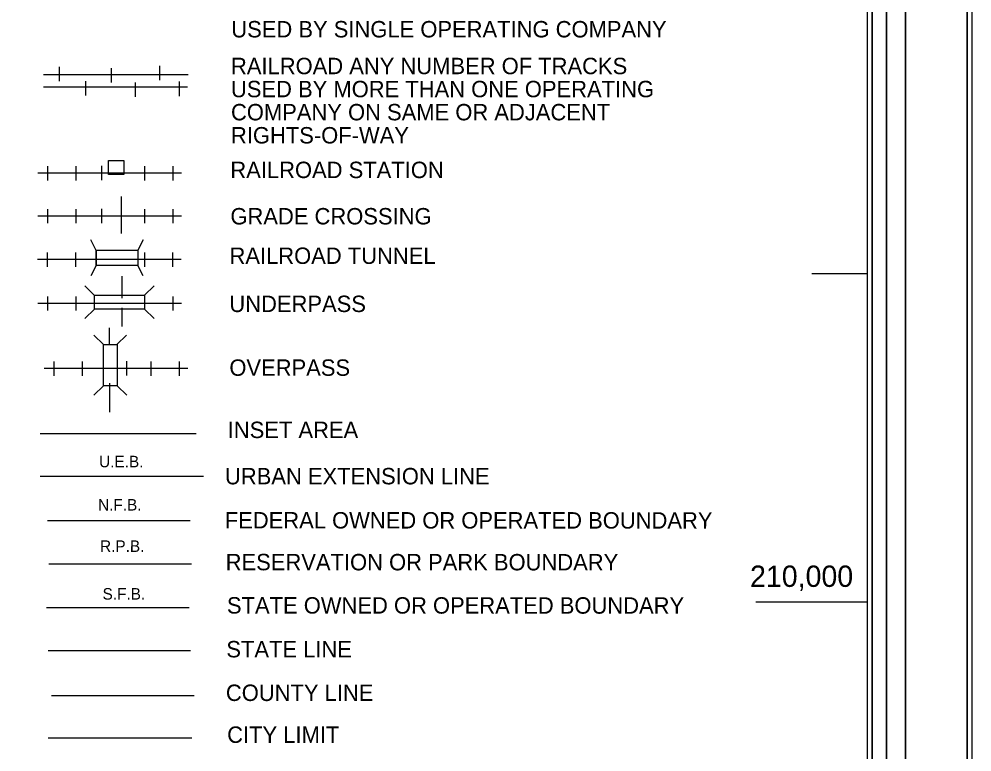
# Model space of a CAD drawing. Extents: x 5197761 to 5514561, y 1890130 to 2080942.
# Drawn here: x 5485527 to 5514561, y 2006843 to 2029172 of the extents above; entities that cross this region are included whole.
import ezdxf

# ---------------------------------------------------------------- set-up
doc = ezdxf.new("R2010")
doc.units = 0
for name, color, linetype in [('Exist Boundary Land Use Forest National US Forest Service', 7, 'Continuous'), ('Exist Boundary Land Use Forest National US Forest Service Label', 7, 'Continuous'), ('Exist Boundary Land Use Forest State Division NC Forest Resources', 7, 'Continuous'), ('Exist Boundary Land Use Forest State Division NC Forest Resources Label', 7, 'Continuous'), ('Exist Boundary Land Use Park State Division NC Parks and Recreation Label', 7, 'Continuous'), ('Exist Boundary Land Use Reservation Indian', 7, 'Continuous'), ('Exist Boundary Land Use Reservation Indian Label', 7, 'Continuous'), ('Exist Boundary Political City Limit New', 7, 'Continuous'), ('Exist Boundary Political City Limit New Label', 7, 'Continuous'), ('Exist Boundary Political CountyLine', 7, 'Continuous'), ('Exist Boundary Political CountyLine Label', 7, 'Continuous'), ('Exist Boundary Political StateLine', 7, 'Continuous'), ('Exist Boundary Political StateLine Label', 7, 'Continuous'), ('Exist Boundary Political Urban Extension UEB', 7, 'Continuous'), ('Exist Boundary Political Urban Extension UEB Label', 7, 'Continuous'), ('Exist Railroad Mainline', 7, 'Continuous'), ('Exist Railroad Mainline Label', 7, 'Continuous'), ('Exist Railroad Station CELL', 7, 'Continuous'), ('Exist Railroad Station Label', 7, 'Continuous'), ('Exist Road Primary NC Attributed', 7, 'Continuous'), ('Exist Road Primary NC Structure Tunnel CELL', 7, 'Continuous'), ('Map Preparation Base StatePlane Tick Label', 7, 'Continuous'), ('Map Preparation Base StatePlane Tick Mark', 7, 'Continuous'), ('Map Preparation Border Antique Large Shape', 7, 'Continuous'), ('Map Preparation Border Antique Small Shape', 7, 'Continuous'), ('Map Preparation Border Black Inside Shape', 7, 'Continuous'), ('Map Preparation Border Black Middle Shape', 7, 'Continuous'), ('Map Preparation Border Black Outside Shape', 7, 'Continuous'), ('Map Preparation Boundary City Limit Buffer Line', 7, 'Continuous'), ('Map Preparation Inset Border', 7, 'Continuous'), ('Map Preparation Inset Cut Line', 7, 'Continuous'), ('Map Preparation Inset Label', 7, 'Continuous')]:
    doc.layers.add(name, color=color, linetype=linetype)

msp = doc.modelspace()

# ---------------------------------------------------------------- linework, layer by layer
at = {"layer": 'Exist Boundary Land Use Forest National US Forest Service'}
msp.add_line((5486395, 2013896), (5490739, 2013896), dxfattribs=at)
at = {"layer": 'Exist Boundary Land Use Forest State Division NC Forest Resources'}
msp.add_line((5486362, 2011244), (5490705, 2011244), dxfattribs=at)
at = {"layer": 'Exist Boundary Land Use Reservation Indian'}
msp.add_line((5486434, 2012576), (5490778, 2012576), dxfattribs=at)
at = {"layer": 'Exist Boundary Political City Limit New'}
msp.add_line((5486412, 2007270), (5490788, 2007270), dxfattribs=at)
at = {"layer": 'Exist Boundary Political CountyLine'}
msp.add_line((5486518, 2008568), (5490862, 2008567), dxfattribs=at)
at = {"layer": 'Exist Boundary Political StateLine'}
msp.add_line((5486410, 2009938), (5490755, 2009937), dxfattribs=at)
at = {"layer": 'Exist Boundary Political Urban Extension UEB'}
msp.add_lwpolyline([(5491145, 2015233), (5490921, 2015233), (5486172, 2015233)], dxfattribs=at)
at = {"layer": 'Exist Railroad Mainline'}
for p, q in [((5489802, 2027748), (5489802, 2027307)), ((5490684, 2027471), (5486271, 2027471)), ((5486753, 2027721), (5486753, 2027280)), ((5488331, 2027681), (5488331, 2027240)), ((5487555, 2027280), (5487555, 2026839)), ((5489066, 2027240), (5489066, 2026799)), ((5490403, 2027267), (5490403, 2026825)), ((5490655, 2027095), (5486268, 2027095)), ((5486392, 2024692), (5486392, 2024257)), ((5487253, 2024692), (5487253, 2024257)), ((5488041, 2024702), (5488041, 2024266)), ((5489350, 2024692), (5489350, 2024257)), ((5490212, 2024692), (5490212, 2024257)), ((5490473, 2024474), (5486096, 2024474)), ((5488041, 2023393), (5488041, 2022958)), ((5490473, 2023166), (5486096, 2023166)), ((5486392, 2023384), (5486392, 2022949)), ((5487253, 2023384), (5487253, 2022949)), ((5489350, 2023384), (5489350, 2022949)), ((5486388, 2022061), (5486388, 2021626)), ((5487249, 2022061), (5487249, 2021626)), ((5489346, 2022061), (5489346, 2021626)), ((5490207, 2022061), (5490207, 2021626)), ((5490469, 2021843), (5486092, 2021843)), ((5490473, 2020507), (5486096, 2020507)), ((5486392, 2020724), (5486392, 2020289)), ((5487253, 2020724), (5487253, 2020289)), ((5490212, 2020724), (5490212, 2020289)), ((5488801, 2018750), (5488801, 2018314)), ((5490668, 2018522), (5486291, 2018522)), ((5486587, 2018740), (5486587, 2018305)), ((5487448, 2018740), (5487448, 2018305)), ((5489546, 2018740), (5489546, 2018305)), ((5490407, 2018740), (5490407, 2018305))]:
    msp.add_line(p, q, dxfattribs=at)
at = {"layer": 'Exist Railroad Station CELL'}
msp.add_lwpolyline([(5488255, 2024865), (5488721, 2024865), (5488721, 2024439), (5488255, 2024439)], close=True, dxfattribs=at)
at = {"layer": 'Exist Road Primary NC Attributed'}
for p, q in [((5488647, 2022640), (5488647, 2023771)), ((5488668, 2020667), (5488668, 2021336)), ((5488668, 2019806), (5488668, 2020370)), ((5488284, 2019234), (5488284, 2019764)), ((5488293, 2017199), (5488293, 2018076))]:
    msp.add_line(p, q, dxfattribs=at)
at = {"layer": 'Exist Road Primary NC Structure Tunnel CELL'}
for p, q in [((5487876, 2022121), (5487716, 2022442)), ((5489306, 2022450), (5489146, 2022130)), ((5487876, 2022121), (5487876, 2021669)), ((5489146, 2022130), (5489146, 2021667)), ((5487876, 2021669), (5487716, 2021349)), ((5489306, 2021346), (5489146, 2021667)), ((5487827, 2020749), (5487536, 2021040)), ((5489644, 2021048), (5489353, 2020757)), ((5487827, 2020338), (5487536, 2020047)), ((5489644, 2020045), (5489353, 2020336)), ((5488097, 2019252), (5487806, 2019544)), ((5488508, 2019252), (5488799, 2019544)), ((5487804, 2017711), (5488095, 2018002)), ((5488807, 2017711), (5488516, 2018002))]:
    msp.add_line(p, q, dxfattribs=at)
for points in [[(5489146, 2021667), (5487876, 2021667), (5487876, 2022130), (5489146, 2022130)], [(5489353, 2020336), (5487827, 2020336), (5487827, 2020757), (5489353, 2020757)], [(5488095, 2018002), (5488095, 2019252), (5488516, 2019252), (5488516, 2018002)]]:
    msp.add_lwpolyline(points, close=True, dxfattribs=at)
at = {"layer": 'Map Preparation Base StatePlane Tick Mark'}
for p, q in [((5509679, 2021420), (5511378, 2021420)), ((5507980, 2011420), (5511378, 2011420))]:
    msp.add_line(p, q, dxfattribs=at)
at = {"layer": 'Map Preparation Border Antique Large Shape'}
msp.add_lwpolyline([(5197907, 2074783), (5207205, 2074783), (5207205, 1892697), (5512539, 1892697), (5512539, 2072359), (5207205, 2072359), (5207205, 2074783), (5514414, 2074783), (5514414, 1890276), (5197907, 1890276)], close=True, dxfattribs=at)
at = {"layer": 'Map Preparation Border Antique Small Shape'}
msp.add_lwpolyline([(5207791, 2071720), (5208220, 2071720), (5208220, 1893712), (5511524, 1893712), (5511524, 2071291), (5208220, 2071291), (5208220, 2071720), (5207791, 2071720), (5511953, 2071720), (5511953, 1893283), (5208220, 1893283), (5207791, 1893283)], close=True, dxfattribs=at)
at = {"layer": 'Map Preparation Border Black Inside Shape'}
msp.add_lwpolyline([(5208220, 2071291), (5511524, 2071291), (5511524, 1893712), (5208366, 1893712), (5208366, 1893858), (5511378, 1893858), (5511378, 2071145), (5208366, 2071145), (5208366, 1893858), (5208366, 1893712), (5208220, 1893712), (5208220, 1893858)], close=True, dxfattribs=at)
at = {"layer": 'Map Preparation Border Black Middle Shape'}
msp.add_lwpolyline([(5207205, 2072359), (5512539, 2072359), (5512539, 1892697), (5511953, 1892697), (5207791, 1892697), (5207791, 1893283), (5511953, 1893283), (5511953, 2071720), (5207791, 2071720), (5207791, 1892697), (5207205, 1892697)], close=True, dxfattribs=at)
at = {"layer": 'Map Preparation Border Black Outside Shape'}
msp.add_lwpolyline([(5197761, 2074930), (5514561, 2074930), (5514561, 1890130), (5197907, 1890130), (5197907, 1890276), (5514414, 1890276), (5514414, 2074783), (5197907, 2074783), (5197907, 1890130), (5197761, 1890130)], close=True, dxfattribs=at)
at = {"layer": 'Map Preparation Boundary City Limit Buffer Line'}
msp.add_line((5486499, 2007270), (5490788, 2007270), dxfattribs=at)
at = {"layer": 'Map Preparation Inset Border'}
msp.add_line((5490212, 2023384), (5490212, 2022949), dxfattribs=at)
at = {"layer": 'Map Preparation Inset Cut Line'}
msp.add_line((5490921, 2016539), (5486172, 2016539), dxfattribs=at)

# ---------------------------------------------------------------- texts
at = {"layer": 'Exist Boundary Land Use Forest National US Forest Service Label'}
for s, height, rotation, p in [('N.F.B.', 350, 359.98, (5487933, 2014199)), ('FEDERAL OWNED OR OPERATED BOUNDARY', 500, 359.9792, (5491795, 2013653))]:
    msp.add_text(s, height=height, rotation=rotation, dxfattribs=at).set_placement(p)
at = {"layer": 'Exist Boundary Land Use Forest State Division NC Forest Resources Label'}
msp.add_text('S.F.B.', height=350, rotation=359.98, dxfattribs=at).set_placement((5488071, 2011485))
at = {"layer": 'Exist Boundary Land Use Park State Division NC Parks and Recreation Label'}
msp.add_text('STATE OWNED OR OPERATED BOUNDARY', height=500, rotation=359.9792, dxfattribs=at).set_placement((5491861, 2011060))
at = {"layer": 'Exist Boundary Land Use Reservation Indian Label'}
for s, height, rotation, p in [('R.P.B.', 350, 359.98, (5487994, 2012939)), ('RESERVATION OR PARK BOUNDARY', 500, 359.9792, (5491822, 2012378))]:
    msp.add_text(s, height=height, rotation=rotation, dxfattribs=at).set_placement(p)
at = {"layer": 'Exist Boundary Political City Limit New Label'}
msp.add_text('CITY LIMIT', height=500, dxfattribs=at).set_placement((5491868, 2007119))
at = {"layer": 'Exist Boundary Political CountyLine Label'}
msp.add_text('COUNTY LINE', height=500, dxfattribs=at).set_placement((5491829, 2008396))
at = {"layer": 'Exist Boundary Political StateLine Label'}
msp.add_text('STATE LINE', height=500, dxfattribs=at).set_placement((5491843, 2009724))
at = {"layer": 'Exist Boundary Political Urban Extension UEB Label'}
msp.add_text('U.E.B.', height=350, rotation=359.98, dxfattribs=at).set_placement((5487965, 2015516))
msp.add_text('URBAN EXTENSION LINE', height=500, dxfattribs=at).set_placement((5491802, 2014996))
at = {"layer": 'Exist Railroad Mainline Label'}
for s, p in [('USED BY SINGLE OPERATING COMPANY', (5491994, 2028613)), ('RAILROAD ANY NUMBER OF TRACKS', (5491984, 2027493)), ('USED BY MORE THAN ONE OPERATING', (5491984, 2026790)), ('COMPANY ON SAME OR ADJACENT', (5491984, 2026086)), ('RIGHTS-OF-WAY', (5491984, 2025382)), ('GRADE CROSSING', (5491967, 2022915)), ('RAILROAD TUNNEL', (5491939, 2021712)), ('UNDERPASS', (5491935, 2020246)), ('OVERPASS', (5491935, 2018303))]:
    msp.add_text(s, height=500, dxfattribs=at).set_placement(p)
at = {"layer": 'Exist Railroad Station Label'}
msp.add_text('RAILROAD STATION', height=500, dxfattribs=at).set_placement((5491965, 2024327))
at = {"layer": 'Map Preparation Base StatePlane Tick Label'}
msp.add_text('210,000', height=650, dxfattribs=at).set_placement((5507800, 2011872))
at = {"layer": 'Map Preparation Inset Label'}
msp.add_text('INSET AREA', height=500, dxfattribs=at).set_placement((5491885, 2016406))

doc.saveas('drawing.dxf')
